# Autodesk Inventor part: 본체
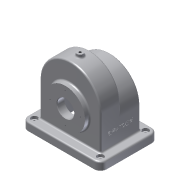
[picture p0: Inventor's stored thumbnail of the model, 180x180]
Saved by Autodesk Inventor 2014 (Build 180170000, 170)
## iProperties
Created: 2017-11
Part Number: 본체
Material: 알루미늄 6061
Document SubType Name: Modeling
Designer: user
Density: 2.71 g/cm^3
Appearance: 알루미늄 - 평지
Mass: 1124.69 g
Surface Area: 1251.26 cm^2
Volume: 415.016 cm^3
Author: user
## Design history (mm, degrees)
sketch "스케치2"
  geometry: L1 (-58, 0)-(-58, -65); L2 (58, 0)-(58, -65); L3 (58, -65)-(-58, -65); A1 r 58 centre (0, 0) between (58, 0) and (-58, 0); 1 further point
  constraints: 6 end point, 2 point on circle, 2 tangent, 1 centre point, 1 coincident, 1 parallel, 1 perpendicular, 1 vertical
  dimensions: "d2" = 116 diameter of A1; "d3" = 65 distance of L1.start L1.end
extrude "돌출1" new body sketch "스케치2" distance "d4" = 38; taper "d5" = 0 deg
sketch "스케치3"
  geometry: L1 (0, 0)-(0, -23); L2 (-58, 0)-(-58, -65) reference; L3 (-58, -65)-(58, -65) reference; L4 (58, -65)-(58, 0) reference; A1 r 58 centre (0, -23) between (58, -23) and (-58, -23)
  constraints: 2 end point, 2 point on circle, 2 point on line, 1 centre point, 1 coincident, 1 vertical
  dimensions: "d7" = 23 distance of L1.start L1.end; "d8" = 116 diameter of A1
extrude "돌출2" join sketch "스케치3" distance "d9" = 38; taper "d10" = 0 deg
sketch "스케치4"
  geometry: L1 (-17, -93)-(133, -93); L2 (133, -93)-(133, 17); L3 (133, 17)-(-17, 17); L4 (-17, 17)-(-17, -93); L5 (-17, -93)-(133, 17); L6 (133, -93)-(-17, 17); 1 further point
  constraints: 12 end point, 2 midpoint, 2 parallel, 1 horizontal, 1 perpendicular
  dimensions: "d11" = 110 distance of L3.end L1.start; "d12" = 150 distance of L1.start L1.end
extrude "돌출3" join sketch "스케치4" distance "d13" = 15; taper "d14" = 0 deg
fillet "모깎기1" dims "d15" = 12
sketch "스케치5"
  geometry: L1 (63, -80)-(-63, -80) reference; L2 (0, -80)-(0, -15); C1 r 37.5 at (0, -15); 1 further point
  constraints: 2 end point, 1 centre point, 1 coincident, 1 midpoint, 1 perpendicular
  dimensions: "d17" = 65 distance of L2.start L2.end; "d18" = 75 diameter of C1
extrude "돌출4" join sketch "스케치5" distance "d19" = 9; taper "d20" = 0 deg
sketch "스케치6"
  geometry: L1 (63, -80)-(-63, -80) reference; L2 (0, -80)-(0, -15); C1 r 31 at (0, -15); 1 further point
  constraints: 2 end point, 1 centre point, 1 coincident, 1 midpoint, 1 perpendicular
  dimensions: "d21" = 65 distance of L2.start L2.end; "d22" = 62 diameter of C1
extrude "돌출5" join sketch "스케치6" distance "d23" = 10; taper "d24" = 0 deg
fillet "모깎기2" dims "d16" = 3
node "작업 평면1"
sketch "스케치8"
  geometry: L1 (-53, 0)-(-53, -89.092); L2 (-53, -89.092)-(53, -89.092); L3 (53, -89.092)-(53, 0); A1 r 53 centre (0, 0) between (53, 0) and (-53, 0); 1 further point
  constraints: 6 end point, 2 point on circle, 2 tangent, 1 centre point, 1 coincident, 1 perpendicular, 1 vertical
  dimensions: "d39" = 106 diameter of A1
extrude "돌출6" cut sketch "스케치8" distance "d40" = 28; taper "d41" = 0 deg
sketch "스케치9"
  geometry: L1 (0, 0)-(0, -23); L2 (-53, -23)-(-53, -80); L3 (-53, -80)-(53, -80); L4 (53, -80)-(53, -23); L5 (-63, -80)-(-75, -80) reference; L6 (-63, -80)-(63, -80) reference; L7 (75, -80)-(63, -80) reference; L8 (63, -80)-(75, -80) reference; L9 (63, -80)-(-63, -80) reference; L10 (-75, -80)-(-63, -80) reference; A1 r 53 centre (0, -23) between (53, -23) and (-53, -23)
  constraints: 8 end point, 2 point on circle, 2 tangent, 1 centre point, 1 coincident, 1 parallel, 1 perpendicular, 1 vertical
  dimensions: "d42" = 23 distance of L1.start L1.end; "d43" = 106 diameter of A1
extrude "돌출7" cut sketch "스케치9" distance "d44" = 38; taper "d45" = 0 deg
sketch "스케치7"
  geometry: L1 (-10.374, 37.577)-(21.813, -22.429); L2 (58, 3)-(58, 35) reference; L3 (22.5, 41)-(22.5, 47) reference; L4 (35, -3)-(35, -35) reference; L5 (16, -41)-(16, -48) reference; L6 (35, -3)-(35, -35) reference; L7 (-80, -55)-(-80, -43) reference; L8 (-80, -43)-(-80, -55) reference; L9 (-80, -43)-(-80, 43) reference; L10 (-80, 55)-(-80, 43) reference; L11 (-80, 43)-(-80, 55) reference; L12 (-80, 43)-(-80, -43) reference; L13 (0, 38)-(-62, 38) reference; L14 (0, 38)-(0, 38) reference; L15 (-62, 38)-(0, 38) reference; L16 (25.5, 38)-(-55.5, 38) reference; L17 (55, 0)-(3.63, 0) reference; L18 (22.5, 47)-(-52.5, 47) reference; L19 (-46, -48)-(16, -48) reference; L20 (-15, -48)-(-15, 47); L21 (1, 47)-(1, 33); L22 (1, 33)-(-15, 33); L23 (1, -48)-(1, -33); L24 (1, -33)-(-15, -33); A1 r 3 centre (55, 35) between (58, 35) and (55, 38) reference; A2 r 3 centre (25.5, 41) between (22.5, 41) and (25.5, 38) reference; A3 r 3 centre (38, -3) between (38, 0) and (35, -3) reference; A4 r 3 centre (55, 3) between (55, 0) and (58, 3) reference; A5 r 3 centre (32, -35) between (32, -38) and (35, -35) reference; A6 r 3 centre (-55.5, 41) between (-55.5, 38) and (-52.5, 41) reference; 1 further point
  constraints: 12 end point, 4 point on line, 3 perpendicular, 2 midpoint, 1 parallel
  dimensions: "d30" = 32 diameter of L21 L20; "d31" = 32 diameter of L23 L20; "d32" = 14 distance of L21.start L21.end; "d33" = 15 distance of L23.start L23.end
revolve "회전1" sketch "스케치7" stored, may be unused: angle "d34" = 90 deg
chamfer "모따기1" distance "d35" = 1; stored, may be unused: second distance "d36" = 2, angle "d37" = 45 deg
fillet "모깎기3" dims "d46" = 3
sketch "스케치10"
  geometry: L1 (53, 19)-(64, 19); L2 (0, 38)-(55, 38) reference; L3 (64, 19)-(64, 13); L4 (64, 13)-(53, 13); L5 (-80, -30)-(-80, 30) reference; L6 (53, 13)-(53, 19); L7 (53, 8)-(53, 30) reference; 2 further points
  constraints: 9 end point, 2 perpendicular, 1 collinear, 1 horizontal, 1 parallel
  dimensions: "d47" = 19 distance between parallel lines of L1 L2; "d48" = 12 diameter of L4 L1; "d49" = 144 distance between parallel lines of L3 L5
revolve "회전2" sketch "스케치10" stored, may be unused: angle "d50" = 90 deg
fillet "모깎기4" dims "d51" = 3
hole "구멍1" diameter "d54" = 4.459; stored, may be unused: countersink angle "d58" = 90 deg, drill point angle "d60" = 0 deg; dims "d52" = 10, "d53" = 10, "d55" = 5, "d56" = 4, "d57" = 2, "d59" = 5
hole "구멍2" diameter "d63" = 5; stored, may be unused: countersink angle "d67" = 90 deg, drill point angle "d69" = 0 deg; dims "d61" = 10, "d62" = 10, "d64" = 5, "d65" = 12, "d66" = 5, "d68" = 5
hole "구멍3" diameter "d72" = 5; stored, may be unused: countersink angle "d76" = 90 deg, drill point angle "d78" = 0 deg; dims "d70" = 10, "d71" = 10, "d73" = 5, "d74" = 12, "d75" = 5, "d77" = 5
hole "구멍4" diameter "d81" = 5; stored, may be unused: countersink angle "d85" = 90 deg, drill point angle "d87" = 0 deg; dims "d79" = 10, "d80" = 10, "d82" = 5, "d83" = 12, "d84" = 5, "d86" = 5
hole "구멍5" diameter "d90" = 5; stored, may be unused: countersink angle "d94" = 90 deg, drill point angle "d96" = 0 deg; dims "d88" = 10, "d89" = 10, "d91" = 5, "d92" = 12, "d93" = 5, "d95" = 5
sketch "스케치13"
  geometry: L1 (-29, 0)-(29, 0); L2 (0, 29)-(0, -29); C1 r 16 at (0, 0) reference; A1 r 29 centre (0, 0) between (-29, 0) and (29, 0); 1 further point
  constraints: 4 end point, 4 point on circle, 1 centre point, 1 coincident, 1 horizontal, 1 perpendicular
  dimensions: "d97" = 58 diameter of A1
hole "구멍6" sketch "스케치13" at (29, 0), (0, 29), (-29, 0), (0, -29) diameter "d98" = 2.459; stored, may be unused: countersink angle "d102" = 90 deg, drill point angle "d104" = 118 deg; dims "d99" = 6, "d100" = 12, "d101" = 5, "d103" = 8
sketch "스케치14"
  geometry: L1 (-26, 0)-(26, 0); L2 (0, 26)-(0, -26); C1 r 16 at (0, 0) reference; A1 r 26 centre (0, 0) between (-26, 0) and (26, 0); 1 further point
  constraints: 4 end point, 4 point on circle, 1 centre point, 1 coincident, 1 horizontal, 1 perpendicular
  dimensions: "d105" = 52 diameter of A1
hole "구멍7" sketch "스케치14" at (0, 26), (-26, 0), (0, -26), (26, 0) diameter "d106" = 2.459; stored, may be unused: countersink angle "d110" = 90 deg, drill point angle "d112" = 118 deg; dims "d107" = 6, "d108" = 12, "d109" = 5, "d111" = 8
sketch "스케치15"
  geometry: L1 (-3, 62)-(-3, 0) reference; L2 (78, -18)-(-8, -18) reference; 2 further points
  constraints: 1 other
  dimensions: "d113" = 38 distance from line of point (35, 22) L1; "d114" = 40 distance from line of point (35, 22) L2
extrude "돌출8" join sketch "스케치15" distance "d115" = 0.5; taper "d116" = 0 deg
node "솔리드1"
node "투영된 루프1"
node "투영된 루프2"
node "투영된 루프3"
other parameters: "d38" = -33
